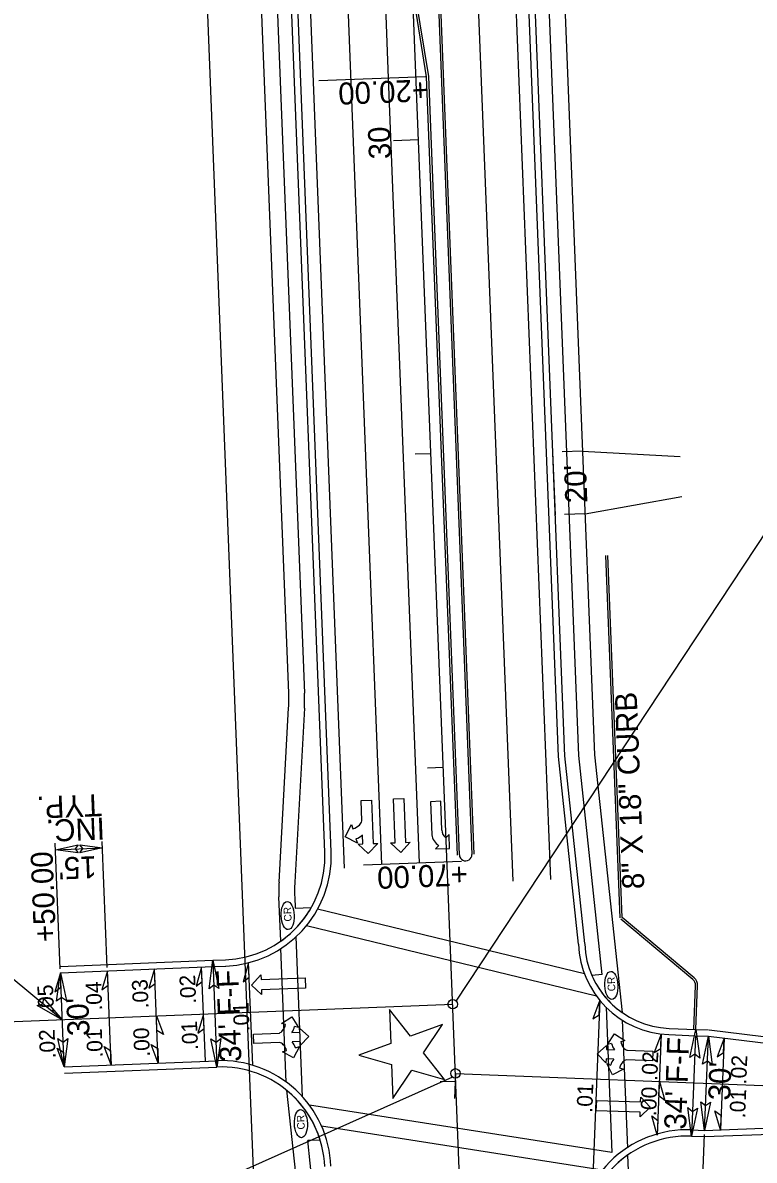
# Model space of a CAD drawing. Extents: x 1627861 to 1629601, y 761281 to 766239.
# Drawn here: x 1628306.1 to 1628539, y 763149.5 to 763511.7 of the extents above; entities that cross this region are included whole.
import ezdxf

# ---------------------------------------------------------------- set-up
doc = ezdxf.new("R2010")
doc.units = 0
for name, color, linetype in [('Exist Other Culture Sign Leader', 7, 'Continuous'), ('Exist Property Tie Line Leader', 7, 'Continuous'), ('Exist Property Tie Line Text', 7, 'Continuous'), ('Exist Right of Way Line Leader', 7, 'Continuous'), ('Exist Right of Way Monument Leader', 7, 'Continuous'), ('Exist Right of Way Monument Text', 7, 'Continuous'), ('Exist Utilities Gas Meter CELL', 7, 'Continuous'), ('Exist Utilities Gas Meter Cogo Elevation', 7, 'Continuous'), ('Exist Utilities Gas Meter Cogo Number', 7, 'Continuous'), ('Exist Utilities Gas UG Line', 7, 'Continuous'), ('Exist Utilities Other Unknown UG SUE Text', 7, 'Continuous'), ('Exist Utilities Power UG Cable SUE LOS B Cogo Elevation', 7, 'Continuous'), ('Exist Utilities Power UG Cable SUE LOS B Cogo Point CELL', 7, 'Continuous'), ('Exist Utilities Telephone UG Cable SUE LOS B Cogo Comment', 7, 'Continuous'), ('Exist Utilities Telephone UG Cable SUE LOS B Cogo Number', 7, 'Continuous'), ('Exist Utilities Telephone UG Cable SUE LOS B Cogo Point CELL', 7, 'Continuous'), ('Exist Utilities Water Fire Hydrant Cogo Elevation', 7, 'Continuous'), ('Exist Utilities Water Fire Hydrant Cogo Number', 7, 'Continuous'), ('Exist Utilities Water Meter Cogo Elevation', 7, 'Continuous'), ('Exist Utilities Water UG Line SUE LOS B Cogo Number', 7, 'Continuous'), ('Exist Utilities Water Valve CELL', 7, 'Continuous'), ('Scratch_Level_0', 7, 'Continuous'), ('Scratch_Level_1', 7, 'Continuous'), ('Typical Terminator CELL', 7, 'Continuous')]:
    doc.layers.add(name, color=color, linetype=linetype)

msp = doc.modelspace()

# ---------------------------------------------------------------- linework, layer by layer
at = {"layer": 'Exist Property Tie Line Text'}
for p, q in [((1628436.05, 763374.45), (1628431.05, 763374.26)), ((1628439.99, 763274.53), (1628434.99, 763274.33)), ((1628443.93, 763174.61), (1628438.93, 763174.41))]:
    msp.add_line(p, q, dxfattribs=at)
at = {"layer": 'Exist Right of Way Line Leader'}
for p, q in [((1628444.09, 763200.16), (1628640.24, 763497.24)), ((1628442.93, 763175.97), (1628230.65, 763081.26))]:
    msp.add_line(p, q, dxfattribs=at)
for centre in [(1628442.96, 763199.17), (1628443.83, 763177.16)]:
    msp.add_circle(centre, 1.5, dxfattribs=at)
at = {"layer": 'Exist Right of Way Monument Leader'}
for p, q in [((1628424.13, 763264.57), (1628427.43, 763264.69)), ((1628424.63, 763250.58), (1628424.13, 763264.57)), ((1628427.43, 763264.69), (1628427.93, 763250.69)), ((1628413.83, 763264), (1628417.13, 763264.11)), ((1628414.06, 763257.55), (1628413.83, 763264)), ((1628417.13, 763264.11), (1628417.62, 763250.32)), ((1628439.21, 763263.77), (1628435.91, 763263.65)), ((1628435.91, 763263.65), (1628436.29, 763253.1)), ((1628439.54, 763254.62), (1628439.21, 763263.77)), ((1628408.69, 763252.5), (1628410.75, 763256.43)), ((1628410.75, 763256.43), (1628411.2, 763255.05)), ((1628412.62, 763250.44), (1628408.69, 763252.5)), ((1628412.16, 763251.88), (1628412.62, 763250.44)), ((1628412.83, 763250.15), (1628414.32, 763250.2)), ((1628416.09, 763247.17), (1628412.83, 763250.15)), ((1628414.32, 763250.2), (1628414.22, 763253.05)), ((1628419.12, 763250.38), (1628416.09, 763247.17)), ((1628417.62, 763250.32), (1628419.12, 763250.38)), ((1628423.14, 763250.52), (1628424.63, 763250.58)), ((1628426.45, 763247.49), (1628423.14, 763250.52)), ((1628429.43, 763250.75), (1628426.45, 763247.49)), ((1628427.93, 763250.69), (1628429.43, 763250.75)), ((1628441.79, 763253.25), (1628440.78, 763252.16)), ((1628441.9, 763248.75), (1628441.79, 763253.25)), ((1628438.51, 763249.73), (1628437.5, 763248.64)), ((1628437.5, 763248.64), (1628441.9, 763248.75)), ((1628378.88, 763205.25), (1628381.92, 763208.56)), ((1628381.92, 763208.56), (1628381.97, 763207.06)), ((1628381.97, 763207.06), (1628395.97, 763207.52)), ((1628395.97, 763207.52), (1628396.08, 763204.23)), ((1628382.13, 763202.26), (1628378.88, 763205.25)), ((1628396.08, 763204.23), (1628382.08, 763203.76)), ((1628382.08, 763203.76), (1628382.13, 763202.26)), ((1628388.43, 763193.05), (1628391.75, 763195.15)), ((1628389.71, 763192.72), (1628388.43, 763193.05)), ((1628391.75, 763195.15), (1628393.9, 763191.78)), ((1628393.9, 763191.78), (1628392.62, 763192.11)), ((1628379.5, 763189.64), (1628387.78, 763190)), ((1628379.63, 763186.62), (1628379.5, 763189.64)), ((1628391.77, 763190.17), (1628394.26, 763190.28)), ((1628394.26, 763190.28), (1628394.2, 763191.55)), ((1628394.2, 763191.55), (1628397.19, 763188.94)), ((1628397.19, 763188.94), (1628394.44, 763185.99)), ((1628492.28, 763186.3), (1628494.43, 763189.72)), ((1628494.43, 763189.72), (1628497.75, 763187.58)), ((1628387.86, 763186.98), (1628379.63, 763186.62)), ((1628394.39, 763187.26), (1628391.86, 763187.15)), ((1628394.16, 763185.74), (1628392.32, 763182.14)), ((1628392.91, 763185.29), (1628394.16, 763185.74)), ((1628394.44, 763185.99), (1628394.39, 763187.26)), ((1628488.99, 763183.36), (1628491.98, 763186.06)), ((1628491.98, 763186.06), (1628491.93, 763184.8)), ((1628491.93, 763184.8), (1628494.46, 763184.69)), ((1628493.57, 763186.63), (1628492.28, 763186.3)), ((1628497.75, 763187.58), (1628496.47, 763187.24)), ((1628388.82, 763183.99), (1628390.07, 763184.44)), ((1628392.32, 763182.14), (1628388.82, 763183.99)), ((1628491.75, 763180.51), (1628488.99, 763183.36)), ((1628491.8, 763181.78), (1628491.75, 763180.51)), ((1628494.28, 763181.67), (1628491.8, 763181.78)), ((1628506.56, 763181.15), (1628498.28, 763181.5)), ((1628498.45, 763184.52), (1628506.69, 763184.17)), ((1628506.69, 763184.17), (1628506.56, 763181.15)), ((1628493.88, 763176.71), (1628492.03, 763180.26)), ((1628492.03, 763180.26), (1628493.28, 763179.81)), ((1628497.37, 763178.52), (1628493.88, 763176.71)), ((1628496.12, 763178.96), (1628497.37, 763178.52)), ((1628488.69, 763165.25), (1628488.8, 763168.55)), ((1628488.8, 763168.55), (1628502.79, 763168.1)), ((1628502.79, 763168.1), (1628502.84, 763169.6)), ((1628502.84, 763169.6), (1628505.88, 763166.4)), ((1628502.68, 763164.8), (1628488.69, 763165.25)), ((1628505.88, 763166.4), (1628502.63, 763163.3)), ((1628502.63, 763163.3), (1628502.68, 763164.8))]:
    msp.add_line(p, q, dxfattribs=at)
for centre, radius, start, end in [((1628411.6, 763258.1), 2.52, 311.1317, 347.4437), ((1628410.14, 763259.36), 4.43, 283.7683, 314.6218), ((1628442.79, 763254.73), 3.28, 182.0586, 231.7168), ((1628411.11, 763256.2), 4.43, 283.6494, 314.528), ((1628441.43, 763254.08), 5.25, 190.7347, 236.0464), ((1628385.76, 763193.35), 4, 319.9283, 351.141), ((1628388.67, 763192.7), 4, 320.7347, 351.5112), ((1628386.99, 763192.13), 2.28, 290.4204, 323.4184), ((1628387.31, 763184.77), 2.28, 41.5647, 76.3307), ((1628386.19, 763183.45), 4, 14.1246, 45.0548), ((1628389.03, 763184.34), 4, 13.7554, 44.6451), ((1628497.52, 763187.25), 4, 188.8366, 219.7263), ((1628500.42, 763187.89), 4, 189.2058, 220.1359), ((1628499.19, 763186.68), 2.28, 216.6458, 251.4119), ((1628497.16, 763178.89), 4, 135.8159, 166.5924), ((1628498.88, 763179.31), 2.28, 105.5016, 138.4996), ((1628500, 763177.99), 4, 135.0095, 166.2221)]:
    msp.add_arc(centre, radius, start, end, dxfattribs=at)
at = {"layer": 'Exist Right of Way Monument Text'}
for p, q in [((1628476.63, 763278.07), (1628455.4, 763816.44)), ((1628404.27, 763247.66), (1628389.69, 763617.57)), ((1628484.28, 763375.29), (1628515.43, 763373.58)), ((1628485.09, 763355.31), (1628515.93, 763360.79)), ((1628482.99, 763218.28), (1628476.63, 763278.07)), ((1628318.07, 763209.21), (1628366.66, 763211.15)), ((1628366.66, 763211.15), (1628370.69, 763211.31)), ((1628369.65, 763211.27), (1628369.69, 763211.27)), ((1628511.78, 763189.48), (1628520.3, 763189.15)), ((1628520.3, 763189.15), (1628524.36, 763188.98)), ((1628524.36, 763188.98), (1628574.33, 763182.88)), ((1628319.26, 763179.24), (1628367.85, 763181.17)), ((1628523.17, 763159.01), (1628573.11, 763160.91)), ((1628519.11, 763159.17), (1628523.17, 763159.01))]:
    msp.add_line(p, q, dxfattribs=at)
for centre, radius, start, end in [((1628369.3, 763246.28), 35, 272.2802, 2.2582), ((1628512.97, 763219.46), 30, 182.2582, 267.731), ((1628369.24, 763146.2), 35, 2.2582, 92.2802), ((1628517.72, 763124.2), 35, 87.731, 182.2582)]:
    msp.add_arc(centre, radius, start, end, dxfattribs=at)
at = {"layer": 'Exist Utilities Gas Meter CELL'}
for p, q in [((1628486.22, 762102.11), (1628373.12, 764970.45)), ((1628268.7, 763192.24), (1628442.96, 763199.17)), ((1628268.7, 763192.24), (1628442.96, 763199.17)), ((1628443.83, 763177.16), (1628562.52, 763172.46)), ((1628443.83, 763177.16), (1628557.94, 763172.64)), ((1628443.83, 763177.16), (1628557.94, 763172.64))]:
    msp.add_line(p, q, dxfattribs=at)
at = {"layer": 'Exist Utilities Gas Meter Cogo Elevation'}
for p, q in [((1628478.63, 763278.15), (1628457.4, 763816.52)), ((1628402.27, 763247.58), (1628387.69, 763617.49)), ((1628484.98, 763218.49), (1628478.62, 763278.29)), ((1628317.99, 763211.21), (1628366.58, 763213.15)), ((1628366.58, 763213.15), (1628370.61, 763213.31)), ((1628369.57, 763213.27), (1628369.61, 763213.27)), ((1628511.86, 763191.48), (1628520.38, 763191.14)), ((1628319.34, 763177.24), (1628367.93, 763179.17))]:
    msp.add_line(p, q, dxfattribs=at)
for centre, radius, start, end in [((1628369.3, 763246.28), 33, 272.2802, 2.2582), ((1628512.97, 763219.46), 28, 182.2582, 267.731), ((1628369.24, 763146.2), 33, 2.2582, 92.2802), ((1628517.72, 763124.2), 33, 87.731, 182.2582)]:
    msp.add_arc(centre, radius, start, end, dxfattribs=at)
at = {"layer": 'Exist Utilities Gas Meter Cogo Number'}
for points in [[(1628323.75, 763247.41), (1628316.51, 763248.36), (1628323.69, 763249.93), (1628322.82, 763248.61)], [(1628324.25, 763249.91), (1628331.5, 763248.96), (1628324.31, 763247.39), (1628325.18, 763248.71)], [(1628365.39, 763204.09), (1628366.58, 763213.15), (1628368.54, 763204.17), (1628366.89, 763205.25)], [(1628316.88, 763200.16), (1628318.07, 763209.21), (1628320.03, 763200.23), (1628318.38, 763201.32)], [(1628312.7, 763201.14), (1628318.66, 763194.23), (1628310.66, 763198.74), (1628312.57, 763199.25)], [(1628518.47, 763182.21), (1628520.38, 763191.14), (1628521.62, 763182.04), (1628520.06, 763183.25)], [(1628522.46, 763180.05), (1628524.36, 763188.98), (1628525.6, 763179.88), (1628524.05, 763181.09)], [(1628320.45, 763188.29), (1628319.26, 763179.24), (1628317.3, 763188.22), (1628318.95, 763187.13)], [(1628369.12, 763188.23), (1628367.93, 763179.17), (1628365.97, 763188.15), (1628367.62, 763187.07)], [(1628525.08, 763167.94), (1628523.17, 763159.01), (1628521.93, 763168.11), (1628523.49, 763166.9)], [(1628520.94, 763166.1), (1628519.03, 763157.17), (1628517.79, 763166.28), (1628519.34, 763165.06)]]:
    msp.add_lwpolyline(points, close=True, dxfattribs=at)
at = {"layer": 'Exist Utilities Gas UG Line'}
for p, q in [((1628462.18, 763238.38), (1628400.83, 764794.17)), ((1628474.17, 763238.85), (1628412.82, 764794.64)), ((1628408.48, 763242.45), (1628347.37, 764792.06)), ((1628420.44, 763243.74), (1628359.36, 764792.53)), ((1628422.58, 763494.02), (1628418.64, 763593.94)), ((1628426.6, 763544.21), (1628434.57, 763494.49)), ((1628449.84, 763246.9), (1628438.1, 763544.67)), ((1628432.43, 763244.21), (1628422.58, 763494.02)), ((1628434.57, 763494.49), (1628444.34, 763246.68))]:
    msp.add_line(p, q, dxfattribs=at)
at = {"layer": 'Exist Utilities Other Unknown UG SUE Text'}
for p, q in [((1628435.32, 763494.52), (1628427.35, 763544.24)), ((1628437.35, 763544.64), (1628449.09, 763246.87)), ((1628445.09, 763246.71), (1628435.32, 763494.52))]:
    msp.add_line(p, q, dxfattribs=at)
msp.add_arc((1628447.09, 763246.79), 2, 182.2582, 2.2582, dxfattribs=at)
at = {"layer": 'Exist Utilities Power UG Cable SUE LOS B Cogo Elevation'}
msp.add_lwpolyline([(1628423.53, 763179.98), (1628423.96, 763169.18), (1628429.96, 763178.17), (1628440.4, 763175.23), (1628433.68, 763183.74), (1628439.69, 763192.75), (1628429.54, 763189), (1628422.84, 763197.49), (1628423.27, 763186.68), (1628413.1, 763182.92), (1628423.53, 763179.98)], dxfattribs=at)
at = {"layer": 'Exist Utilities Telephone UG Cable SUE LOS B Cogo Comment'}
for p, q in [((1628484.9, 763208.88), (1628399.97, 763229.43)), ((1628488.73, 763201.78), (1628396.39, 763224.12)), ((1628395.17, 763169.72), (1628393.16, 763220.67)), ((1628389.98, 763174.4), (1628388.3, 763216.89)), ((1628491.8, 763198.2), (1628493.62, 763151.91)), ((1628496.96, 763194.08), (1628498.57, 763153.49)), ((1628493.62, 763151.91), (1628397.34, 763167.07)), ((1628490.6, 763146.31), (1628401.24, 763160.39))]:
    msp.add_line(p, q, dxfattribs=at)
at = {"layer": 'Exist Utilities Telephone UG Cable SUE LOS B Cogo Number'}
for p, q in [((1628496.25, 763226.71), (1628491.71, 763342)), ((1628496.92, 763226.74), (1628492.37, 763342.02)), ((1628519.43, 763207.02), (1628496.49, 763226.23)), ((1628519.86, 763207.53), (1628496.92, 763226.74)), ((1628519.71, 763191.17), (1628520.26, 763205.14)), ((1628520.38, 763191.14), (1628520.93, 763205.11))]:
    msp.add_line(p, q, dxfattribs=at)
for radius in [2.33, 3]:
    msp.add_arc((1628517.93, 763205.23), radius, 357.731, 50.0666, dxfattribs=at)
at = {"layer": 'Exist Utilities Telephone UG Cable SUE LOS B Cogo Point CELL'}
for p, q in [((1628520.38, 763191.14), (1628524.44, 763190.98)), ((1628524.6, 763190.97), (1628574.57, 763184.86)), ((1628519.03, 763157.17), (1628523.09, 763157.01)), ((1628523.25, 763157.01), (1628573.19, 763158.91))]:
    msp.add_line(p, q, dxfattribs=at)
at = {"layer": 'Exist Utilities Water Fire Hydrant Cogo Elevation'}
for centre in [(1628390.43, 763227.4), (1628493.48, 763205.16), (1628394.64, 763161.16)]:
    msp.add_ellipse(centre, major_axis=(-0.18, 4.48), ratio=0.462467, dxfattribs=at)
at = {"layer": 'Exist Utilities Water Fire Hydrant Cogo Number'}
for p, q in [((1628376.68, 763217.89), (1628359.91, 763642.43)), ((1628378.53, 763173.02), (1628376.68, 763217.89)), ((1628395.04, 762749.86), (1628378.53, 763173.02))]:
    msp.add_line(p, q, dxfattribs=at)
at = {"layer": 'Exist Utilities Water Meter Cogo Elevation'}
for p, q in [((1628432.11, 763474.38), (1628424.12, 763474.06)), ((1628443.83, 763177.16), (1628443.51, 763169.17))]:
    msp.add_line(p, q, dxfattribs=at)
at = {"layer": 'Exist Utilities Water UG Line SUE LOS B Cogo Number'}
for p, q in [((1628349.24, 763180.43), (1628348.04, 763210.41)), ((1628364.22, 763181.03), (1628363.03, 763211)), ((1628379.29, 763179.73), (1628377.99, 763212.38)), ((1628319.26, 763179.24), (1628318.07, 763209.21)), ((1628334.25, 763179.83), (1628333.05, 763209.81)), ((1628489.79, 763200.42), (1628487.46, 763141.78)), ((1628509.38, 763189.68), (1628508.1, 763157.51)), ((1628529.34, 763188.38), (1628528.19, 763159.2))]:
    msp.add_line(p, q, dxfattribs=at)
at = {"layer": 'Exist Utilities Water Valve CELL'}
for p, q in [((1628465.98, 763840.04), (1628488.12, 763278.53)), ((1628483.12, 763278.33), (1628461.24, 763833.32)), ((1628390.77, 763298.23), (1628377.28, 763640.26)), ((1628382.53, 763633.93), (1628395.77, 763298.19)), ((1628387.69, 763238.05), (1628390.73, 763293.52)), ((1628395.74, 763293.48), (1628392.69, 763238.01)), ((1628490.55, 763208.65), (1628483.14, 763278.33)), ((1628488.15, 763278.53), (1628496.87, 763196.55)), ((1628388.21, 763219.24), (1628387.65, 763233.34)), ((1628392.66, 763233.3), (1628392.8, 763229.71)), ((1628392.8, 763229.71), (1628397.96, 763229.92)), ((1628490.55, 763208.65), (1628487.29, 763208.3)), ((1628390.08, 763171.79), (1628399.06, 763087.33)), ((1628400.79, 763155.89), (1628396.82, 763155.74)), ((1628404.07, 763087.53), (1628396.82, 763155.74)), ((1628498.66, 763151.13), (1628499.22, 763136.93))]:
    msp.add_line(p, q, dxfattribs=at)
for centre, radius, start, end in [((1628340.81, 763296.26), 50, 356.8588, 2.2582), ((1628345.81, 763296.22), 50, 356.8588, 2.2582), ((1628437.61, 763235.31), 50, 176.8588, 182.2582), ((1628442.62, 763235.27), 50, 176.8588, 182.2582), ((1628369.3, 763246.28), 33, 304.9604, 330.2724), ((1628512.97, 763219.46), 28, 203.4876, 234.8988), ((1628369.24, 763146.2), 33, 17.0849, 50.845), ((1628517.72, 763124.2), 33, 125.2948, 148.0029)]:
    msp.add_arc(centre, radius, start, end, dxfattribs=at)
at = {"layer": 'Scratch_Level_0'}
for p, q in [((1628434.31, 763494.48), (1628400.35, 763493.14)), ((1628474.79, 763374.91), (1628475.6, 763354.93)), ((1628318.02, 763210.41), (1628316.43, 763250.4)), ((1628333.01, 763210.87), (1628331.41, 763251)), ((1628316.51, 763248.36), (1628331.5, 763248.96)), ((1628414.62, 763243.51), (1628445.78, 763244.74)), ((1628318.66, 763194.23), (1628270.75, 763233.69)), ((1628366.58, 763213.15), (1628367.93, 763179.17)), ((1628319.26, 763179.28), (1628318.07, 763209.18)), ((1628520.3, 763189.15), (1628519.03, 763157.17)), ((1628523.17, 763159.01), (1628524.36, 763188.98)), ((1628520.93, 763102.29), (1628523.12, 763157.64))]:
    msp.add_line(p, q, dxfattribs=at)
at = {"layer": 'Scratch_Level_1'}
for p, q in [((1628484.28, 763375.29), (1628477.79, 763375.03)), ((1628485.09, 763355.31), (1628478.6, 763355.05))]:
    msp.add_line(p, q, dxfattribs=at)
at = {"layer": 'Typical Terminator CELL'}
for points in [[(1628348.04, 763210.41), (1628346.28, 763204.33), (1628348.23, 763205.79)], [(1628363.03, 763211), (1628361.27, 763204.93), (1628363.21, 763206.38)], [(1628377.99, 763212.38), (1628376.23, 763206.3), (1628378.17, 763207.76)], [(1628318.07, 763209.21), (1628316.31, 763203.14), (1628318.25, 763204.59)], [(1628333.05, 763209.81), (1628331.3, 763203.74), (1628333.24, 763205.19)], [(1628489.79, 763200.42), (1628487.55, 763194.5), (1628489.6, 763195.79)], [(1628363.63, 763196.02), (1628361.87, 763189.94), (1628363.81, 763191.39)], [(1628348.64, 763195.42), (1628350.87, 763189.5), (1628348.82, 763190.8)], [(1628509.38, 763189.68), (1628507.14, 763183.76), (1628509.19, 763185.05)], [(1628529.34, 763188.38), (1628527.11, 763182.46), (1628529.16, 763183.75)], [(1628319.26, 763179.24), (1628317.02, 763185.15), (1628319.08, 763183.86)], [(1628334.25, 763179.83), (1628332.01, 763185.75), (1628334.06, 763184.46)], [(1628349.24, 763180.43), (1628347, 763186.35), (1628349.05, 763185.05)], [(1628508.78, 763174.59), (1628510.54, 763168.52), (1628508.6, 763169.97)], [(1628508.1, 763157.51), (1628506.34, 763163.58), (1628508.29, 763162.13)], [(1628528.19, 763159.2), (1628526.42, 763165.27), (1628528.37, 763163.82)]]:
    msp.add_lwpolyline(points, close=True, dxfattribs=at)

# ---------------------------------------------------------------- texts
at = {"layer": 'Exist Other Culture Sign Leader'}
msp.add_text('8" X 18" CURB', height=7, rotation=92.2582, dxfattribs=at).set_placement((1628504, 763235.93))
at = {"layer": 'Exist Property Tie Line Leader'}
msp.add_text('30', height=7, rotation=92.2582, dxfattribs=at).set_placement((1628423.34, 763468.35))
at = {"layer": 'Exist Utilities Power UG Cable SUE LOS B Cogo Point CELL'}
for s, rotation, p in [('TYP.', 182.2802, (1628331.17, 763266.07)), ('INC.', 182.2802, (1628332.09, 763258.59)), ('+50.00', 92.2802, (1628316.7, 763219.11)), ("15'", 182.2802, (1628329.48, 763246.35)), ("34' F-F", 92.0586, (1628375.73, 763180.91)), ("30' ", 92.0586, (1628327.38, 763189.17)), ("34' F-F", 88.0265, (1628517.27, 763159.19)), ("30'", 88.0265, (1628531.29, 763168.44))]:
    msp.add_text(s, height=7, rotation=rotation, dxfattribs=at).set_placement(p)
at = {"layer": 'Exist Utilities Water Fire Hydrant Cogo Elevation'}
for p in [(1628391.69, 763225.56), (1628494.74, 763203.33), (1628395.89, 763159.32)]:
    msp.add_text('CR', height=2.4, rotation=92.2582, dxfattribs=at).set_placement(p)
at = {"layer": 'Exist Utilities Water UG Line SUE LOS B Cogo Number'}
for s, rotation, p in [('.03', 92.2802, (1628346.16, 763197.94)), ('.02', 92.2802, (1628361.32, 763199.36)), ('.05', 92.2802, (1628316.08, 763196.23)), ('.04', 92.2802, (1628331.41, 763197.22)), ('.01', 92.2802, (1628378.31, 763190.62)), ('.01', 92.2802, (1628361.92, 763184.67)), ('.02', 92.2802, (1628316.57, 763182.02)), ('.01', 92.2802, (1628331.61, 763182.25)), ('.00', 92.2802, (1628346.6, 763182.55)), ('.02', 87.731, (1628508.08, 763174.76)), ('.02', 87.731, (1628536.41, 763173.6)), ('.01', 87.731, (1628487.39, 763164.58)), ('.00', 87.731, (1628507.73, 763163.52)), ('.01', 87.731, (1628536.06, 763162.8))]:
    msp.add_text(s, height=5, rotation=rotation, dxfattribs=at).set_placement(p)
at = {"layer": 'Scratch_Level_0'}
for s, rotation, p in [('+20.00', 182.2582, (1628435.27, 763493.7)), ("20'", 92.2582, (1628485.85, 763358.86)), ('+70.00', 182.2582, (1628447.64, 763244))]:
    msp.add_text(s, height=7, rotation=rotation, dxfattribs=at).set_placement(p)

doc.saveas('drawing.dxf')
